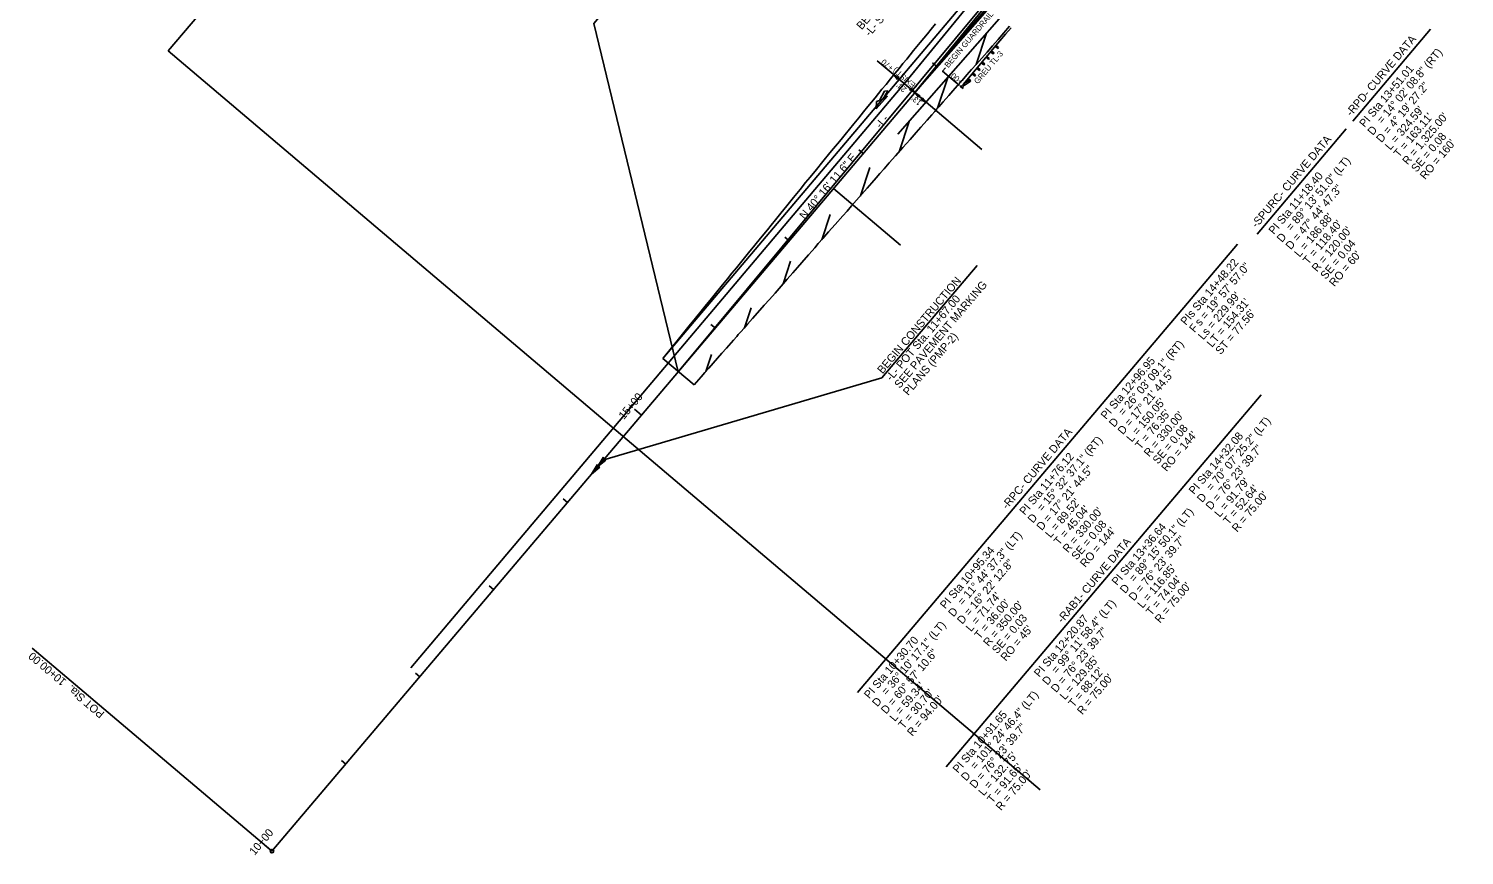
# Model space of a CAD drawing. Extents: x 1761082 to 1764358, y 421907 to 425434.
# Drawn here: x 1761082 to 1762338, y 421907 to 422631 of the extents above; entities that cross this region are included whole.
import ezdxf

# ---------------------------------------------------------------- set-up
doc = ezdxf.new("R2010")
doc.units = 0
for name, color, linetype in [('MARK HOOKS CENTER LEFT TURN ARROW CELL', 7, 'Continuous'), ('MARK HOOKS CENTER STRAIGHT LEFT TURN ARROW CELL', 7, 'Continuous'), ('MARK HOOKS STRAIGHT RIGHT TURN ARROW CELL', 7, 'Continuous'), ('MARK STRAIGHT RIGHT ARROW CELL', 7, 'Continuous'), ('MARK UTURN ARROW CELL', 7, 'Continuous'), ('Prop Horizontal Alignment Tick Large', 7, 'Continuous'), ('Prop Mkg 3ft Min Skp 3ft Wide White', 7, 'Continuous'), ('Prop Mkg 3ft Min Skp 9ft Wide White', 7, 'Continuous'), ('Prop Mkg Skp Wht', 7, 'Continuous'), ('Prop Mkg Solid White Multiple Diagonals V8i', 7, 'Continuous'), ('Prop Mkg Solid Yel Skip LT', 7, 'Continuous'), ('Prop Mkg Solid Yel Skip RT', 7, 'Continuous'), ('Prop Mkg Solid Yellow Diagonals', 7, 'Continuous'), ('Prop Mkg Solid Yellow Edge Line', 7, 'Continuous'), ('Prop Mkg Solid Yellow Lane Line', 7, 'Continuous'), ('Prop Mkg Yld Lin', 7, 'Continuous'), ('Prop Mkr Yel 40ft Spc', 7, 'Continuous'), ('Scratch_Level_0', 7, 'Continuous'), ('Typical Terminator CELL', 7, 'Continuous')]:
    doc.layers.add(name, color=color, linetype=linetype)

msp = doc.modelspace()

# ---------------------------------------------------------------- linework, layer by layer
at = {"layer": 'MARK HOOKS CENTER STRAIGHT LEFT TURN ARROW CELL'}
for p, q in [((1761876.3, 422597.5), (1761872.5, 422600.7)), ((1761811.6, 422521.2), (1761807.8, 422524.4)), ((1761747, 422444.9), (1761743.2, 422448.1)), ((1761682.4, 422368.6), (1761678.5, 422371.8)), ((1761553.1, 422216), (1761549.3, 422219.2)), ((1761488.4, 422139.7), (1761484.6, 422142.9)), ((1761423.8, 422063.4), (1761420, 422066.6)), ((1761359.2, 421987.1), (1761355.4, 421990.3))]:
    msp.add_line(p, q, dxfattribs=at)
at = {"layer": 'MARK STRAIGHT RIGHT ARROW CELL'}
msp.add_line((1761294.5, 421910.8), (1762673, 423537.9), dxfattribs=at)
at = {"layer": 'MARK UTURN ARROW CELL'}
for p, q in [((1762240.1, 422549.7), (1762308.2, 422630.1)), ((1762156.3, 422450.8), (1762234.4, 422542.9)), ((1761806.7, 422049.7), (1762139.1, 422442)), ((1761884.4, 421984.6), (1762160, 422310)), ((1761293.4, 421911.7), (1761084.7, 422088.5))]:
    msp.add_line(p, q, dxfattribs=at)
for points in [[(1761738.9, 422827.3), (1761576.1, 422635.1), (1761650, 422330.4)], [(1761911.5, 422423.4), (1761828, 422324.9), (1761584.7, 422253.3)]]:
    msp.add_lwpolyline(points, dxfattribs=at)
msp.add_circle((1761294.5, 421910.8), 1.5, dxfattribs=at)
at = {"layer": 'Prop Horizontal Alignment Tick Large'}
for p, q in [((1761617.7, 422292.3), (1761611.6, 422297.5)), ((1761294.5, 421910.8), (1761288.4, 421916))]:
    msp.add_line(p, q, dxfattribs=at)
at = {"layer": 'Prop Mkg 3ft Min Skp 3ft Wide White'}
msp.add_line((1761294.5, 421910.8), (1762673, 423537.9), dxfattribs=at)
at = {"layer": 'Prop Mkg 3ft Min Skp 9ft Wide White'}
msp.add_lwpolyline([(1761929.6, 422617.9), (1761931.4, 422619.9), (1761936.3, 422625.6), (1761941.3, 422631.3)], dxfattribs=at)
at = {"layer": 'Prop Mkg Skp Wht'}
msp.add_line((1761663.8, 422318.8), (1761636.4, 422342), dxfattribs=at)
for points in [[(1761875.1, 422634.8), (1761871.3, 422630.2), (1761867.9, 422626), (1761861.7, 422618.5), (1761855.8, 422611.3), (1761849.8, 422603.9), (1761846.5, 422600), (1761843.1, 422595.8), (1761839.5, 422591.3), (1761835.6, 422586.5), (1761831.8, 422581.8), (1761828.2, 422577.5), (1761822.2, 422570), (1761815.9, 422562.3), (1761812.1, 422557.7), (1761808, 422552.6), (1761803.7, 422547.4), (1761799.8, 422542.5), (1761796, 422537.9), (1761792.6, 422533.7), (1761789.2, 422529.7), (1761785.9, 422525.7), (1761782.7, 422521.8), (1761776.5, 422514.2), (1761770.8, 422507.4), (1761765.3, 422500.6), (1761761.4, 422495.8), (1761756.6, 422489.8), (1761750.8, 422482.7), (1761744.9, 422475.4), (1761739.6, 422469), (1761735.1, 422463.4), (1761731.3, 422458.7), (1761727.9, 422454.6), (1761722, 422447.3), (1761716.9, 422441.1), (1761711.4, 422434.4), (1761705.7, 422427.2), (1761700.8, 422421.3), (1761696.9, 422416.6), (1761692.9, 422411.7), (1761688.6, 422406.3), (1761682.6, 422398.9), (1761678.9, 422394.3), (1761674.7, 422389.1), (1761670.1, 422383.4), (1761665, 422377.2), (1761659.6, 422370.5), (1761653.7, 422363.3), (1761647.7, 422355.9), (1761641.6, 422348.3), (1761636.4, 422342)], [(1761663.8, 422318.8), (1761670, 422325.9), (1761673.3, 422329.6), (1761676.8, 422333.6), (1761680.5, 422337.8), (1761684.3, 422342.1), (1761688.2, 422346.5), (1761692.1, 422351), (1761698.3, 422358.1), (1761701.1, 422361.2), (1761702.5, 422362.8), (1761704.7, 422365.3), (1761707.5, 422368.4), (1761710.6, 422371.9), (1761714.9, 422376.8), (1761721.3, 422384.1), (1761725.2, 422388.6), (1761729.7, 422393.6), (1761734.6, 422399.2), (1761740, 422405.3), (1761745.3, 422411.4), (1761750.1, 422416.8), (1761754.4, 422421.7), (1761758.1, 422425.9), (1761763.8, 422432.5), (1761767, 422436.2), (1761769.4, 422438.9), (1761772.5, 422442.5), (1761776.5, 422447), (1761781.5, 422452.7), (1761787.3, 422459.3), (1761793.9, 422466.8), (1761797.6, 422470.9), (1761801.6, 422475.4), (1761805.9, 422480.4), (1761810.6, 422485.7), (1761815.2, 422490.9), (1761819.4, 422495.7), (1761823.1, 422500), (1761826.4, 422503.7), (1761830, 422507.8), (1761834.5, 422513), (1761840, 422519.2), (1761846.5, 422526.5), (1761852.8, 422533.7), (1761858.1, 422539.7), (1761862.3, 422544.4), (1761867.8, 422550.6), (1761871.7, 422555), (1761874.3, 422558), (1761876.3, 422560.4), (1761878, 422562.2), (1761879.7, 422564.1), (1761881.8, 422566.5), (1761886.7, 422572.1), (1761890.3, 422576.1), (1761894.3, 422580.7), (1761898.3, 422585.3), (1761902.4, 422590), (1761906.6, 422594.7), (1761910.9, 422599.6), (1761915.4, 422604.7), (1761920.1, 422610.1), (1761924.9, 422615.6), (1761929.9, 422621.2), (1761934.8, 422626.9), (1761939.8, 422632.6)]]:
    msp.add_lwpolyline(points, dxfattribs=at)
at = {"layer": 'Prop Mkg Solid White Multiple Diagonals V8i'}
for p, q in [((1761203.6, 422611), (1763595.3, 425434.2)), ((1761636.4, 422342), (1762107.9, 422898.7)), ((1761650, 422330.4), (1762065.6, 422830.3)), ((1761847.7, 422582.3), (1762056.3, 422837.9)), ((1761203.6, 422611), (1761966.6, 421964.6)), ((1761915.5, 422524.9), (1761856.9, 422574.6)), ((1761844.4, 422441), (1761785.8, 422490.7))]:
    msp.add_line(p, q, dxfattribs=at)
at = {"layer": 'Prop Mkg Solid Yel Skip RT'}
for p, q in [((1761824, 422602.5), (1761838, 422590.6)), ((1761838.5, 422590.1), (1761856.9, 422574.6)), ((1761866.7, 422566), (1761856.9, 422574.6)), ((1761856.9, 422574.6), (1761866.7, 422566))]:
    msp.add_line(p, q, dxfattribs=at)
msp.add_lwpolyline([(1761895.9, 422580.8), (1761881.2, 422593.3), (1761883.8, 422596.4)], dxfattribs=at)
at = {"layer": 'Prop Mkg Solid Yellow Diagonals'}
for p, q in [((1761826.1, 422567.8), (1761830.5, 422575.8)), ((1761833.4, 422576.2), (1761829.3, 422569)), ((1761830.5, 422575.8), (1761833.4, 422576.2)), ((1761832.9, 422571.4), (1761823.2, 422560.3)), ((1761823.2, 422560.3), (1761823.5, 422566.7)), ((1761823.5, 422566.7), (1761826.1, 422567.8)), ((1761829.3, 422569), (1761832.9, 422571.4))]:
    msp.add_line(p, q, dxfattribs=at)
at = {"layer": 'Prop Mkg Solid Yellow Edge Line'}
for p, q in [((1762055, 422836.3), (1761848.9, 422583.8)), ((1761848.9, 422583.8), (1761416.1, 422071.3))]:
    msp.add_line(p, q, dxfattribs=at)
at = {"layer": 'Prop Mkg Solid Yellow Lane Line'}
for points in [[(1761841.8, 422586.1), (1761838.5, 422590.1), (1761843, 422587.4), (1761841.9, 422587.2)], [(1761853.6, 422578.6), (1761856.9, 422574.6), (1761852.4, 422577.2), (1761853.5, 422577.5)], [(1761860.1, 422570.6), (1761856.9, 422574.6), (1761861.3, 422571.9), (1761860.3, 422571.6)], [(1761863.4, 422570.1), (1761866.7, 422566), (1761862.2, 422568.7), (1761863.3, 422569)]]:
    msp.add_lwpolyline(points, close=True, dxfattribs=at)
at = {"layer": 'Prop Mkg Yld Lin'}
for p, q in [((1761929.6, 422617.9), (1761899.4, 422582.1)), ((1761927.9, 422615.9), (1761927.3, 422615.2)), ((1761927.3, 422615.2), (1761929.6, 422613.2)), ((1761927.3, 422615.2), (1761928.4, 422614.2)), ((1761929.1, 422615), (1761927.3, 422615.2)), ((1761927.9, 422615.9), (1761930.2, 422614)), ((1761928.4, 422614.2), (1761927.9, 422615.9)), ((1761929.1, 422615), (1761928.4, 422614.2)), ((1761928.4, 422614.2), (1761930.2, 422614)), ((1761929.6, 422613.2), (1761929.1, 422615)), ((1761930.2, 422614), (1761929.6, 422613.2)), ((1761915.7, 422601.5), (1761915.1, 422600.7)), ((1761915.1, 422600.7), (1761917.4, 422598.8)), ((1761916.9, 422600.5), (1761915.1, 422600.7)), ((1761915.7, 422601.5), (1761918.1, 422599.5)), ((1761915.7, 422601.5), (1761916.3, 422599.7)), ((1761919.2, 422605.5), (1761921.5, 422603.6)), ((1761921, 422605.3), (1761919.2, 422605.5)), ((1761919.8, 422606.3), (1761922.1, 422604.3)), ((1761919.8, 422606.3), (1761920.3, 422604.5)), ((1761921, 422605.3), (1761920.3, 422604.5)), ((1761920.3, 422604.5), (1761922.1, 422604.3)), ((1761921.5, 422603.6), (1761921, 422605.3)), ((1761922.1, 422604.3), (1761921.5, 422603.6)), ((1761923.2, 422610.3), (1761925.6, 422608.4)), ((1761925, 422610.1), (1761923.2, 422610.3)), ((1761923.9, 422611.1), (1761926.2, 422609.1)), ((1761923.9, 422611.1), (1761924.4, 422609.4)), ((1761925, 422610.1), (1761924.4, 422609.4)), ((1761924.4, 422609.4), (1761926.2, 422609.1)), ((1761925.6, 422608.4), (1761925, 422610.1)), ((1761926.2, 422609.1), (1761925.6, 422608.4)), ((1761907, 422591.1), (1761909.3, 422589.1)), ((1761908.8, 422590.9), (1761907, 422591.1)), ((1761907.6, 422591.8), (1761909.9, 422589.9)), ((1761907.6, 422591.8), (1761908.1, 422590.1)), ((1761908.8, 422590.9), (1761908.1, 422590.1)), ((1761908.1, 422590.1), (1761909.9, 422589.9)), ((1761909.3, 422589.1), (1761908.8, 422590.9)), ((1761909.9, 422589.9), (1761909.3, 422589.1)), ((1761911, 422595.9), (1761913.4, 422593.9)), ((1761912.9, 422595.6), (1761911, 422595.9)), ((1761911.7, 422596.7), (1761914.1, 422594.6)), ((1761911.7, 422596.7), (1761912.2, 422594.9)), ((1761912.9, 422595.6), (1761912.2, 422594.9)), ((1761912.2, 422594.9), (1761914.1, 422594.6)), ((1761913.4, 422593.9), (1761912.9, 422595.6)), ((1761914.1, 422594.6), (1761913.4, 422593.9)), ((1761916.9, 422600.5), (1761916.3, 422599.7)), ((1761916.3, 422599.7), (1761918.1, 422599.5)), ((1761917.4, 422598.8), (1761916.9, 422600.5)), ((1761918.1, 422599.5), (1761917.4, 422598.8)), ((1761898.1, 422580.5), (1761896.7, 422580.2)), ((1761896.7, 422580.2), (1761898.9, 422578.3)), ((1761899.5, 422582.1), (1761898.1, 422580.5)), ((1761898.9, 422578.3), (1761899, 422579.7)), ((1761899, 422579.7), (1761900.4, 422581.2)), ((1761899.1, 422581.7), (1761900.3, 422580.8)), ((1761899.1, 422581.7), (1761900.9, 422581.5)), ((1761899.9, 422581.6), (1761899.5, 422582.1)), ((1761904.1, 422585.3), (1761899.8, 422582.5)), ((1761899.8, 422582.5), (1761900.9, 422581.5)), ((1761900.3, 422580.8), (1761899.8, 422582.5)), ((1761900.4, 422581.2), (1761899.9, 422581.6)), ((1761900.9, 422581.5), (1761900.3, 422580.8)), ((1761900.9, 422581.5), (1761900.6, 422581.2)), ((1761905.3, 422584.3), (1761900.9, 422581.5)), ((1761902.9, 422586.3), (1761905.3, 422584.3)), ((1761904.7, 422586), (1761902.9, 422586.3)), ((1761903.6, 422587), (1761905.9, 422585)), ((1761903.6, 422587), (1761904.1, 422585.3)), ((1761904.7, 422586), (1761904.1, 422585.3)), ((1761904.1, 422585.3), (1761905.9, 422585)), ((1761905.3, 422584.3), (1761904.7, 422586)), ((1761905.9, 422585), (1761905.3, 422584.3))]:
    msp.add_line(p, q, dxfattribs=at)
at = {"layer": 'Scratch_Level_0'}
for p, q in [((1761856.9, 422574.6), (1762095.5, 422846.9)), ((1761842.2, 422538.1), (1762105.3, 422838.4)), ((1761856.9, 422574.6), (1762065.6, 422830.3)), ((1761919.7, 422626.6), (1761910.7, 422599.3)), ((1761888.8, 422613.7), (1761893.1, 422615.9)), ((1761885.8, 422587.9), (1761876.9, 422561)), ((1761851.9, 422549.2), (1761843.2, 422522.8)), ((1761817.6, 422509.1), (1761809.3, 422484.2)), ((1761782.8, 422467.9), (1761775.6, 422445.9)), ((1761748.2, 422427), (1761741.7, 422407.3)), ((1761713.6, 422386.2), (1761707.9, 422368.8)), ((1761679, 422345.3), (1761674.1, 422330.5))]:
    msp.add_line(p, q, dxfattribs=at)
at = {"layer": 'Typical Terminator CELL'}
for points in [[(1761581.3, 422246.8), (1761574, 422240.7), (1761578.9, 422249), (1761579.4, 422247)], [(1761586.7, 422253.1), (1761579.4, 422247), (1761584.2, 422255.3), (1761584.7, 422253.3)]]:
    msp.add_lwpolyline(points, close=True, dxfattribs=at)

# ---------------------------------------------------------------- texts
at = {"layer": 'MARK HOOKS CENTER LEFT TURN ARROW CELL'}
msp.add_text('N 40%%d 16\' 11.6" E', height=7, rotation=49.7301, dxfattribs=at).set_placement((1761760.5, 422463.2))
at = {"layer": 'MARK HOOKS STRAIGHT RIGHT TURN ARROW CELL'}
for s, p in [('-L-', (1761827, 422542.8)), ('15+00', (1761602.4, 422288.1)), ('10+00', (1761279.3, 421906.7))]:
    msp.add_text(s, height=7, rotation=49.7301, dxfattribs=at).set_placement(p)
at = {"layer": 'MARK UTURN ARROW CELL'}
for s, rotation, p in [('BEGIN GRADE', 49.7301, (1761810.5, 422629.1)), ('-L- Sta. 21+69.00', 49.7301, (1761817.5, 422623.2)), ('BEGIN CONSTRUCTION', 49.7301, (1761828.7, 422328)), ('SEE PAVEMENT MARKING', 49.7301, (1761843.7, 422315.3)), ('-L- POT Sta. 11+67.00', 49.7301, (1761836.2, 422321.7)), ('PLANS (PMP-2)', 49.7301, (1761851.2, 422309)), ('POT Sta.  10+00.00', 139.7301, (1761148.5, 422031.9))]:
    msp.add_text(s, height=7, rotation=rotation, dxfattribs=at).set_placement(p)
at = {"layer": 'Prop Mkg Solid Yel Skip LT'}
for s, rotation, p in [('BEGIN GUARDRAIL', 49.7301, (1761886.2, 422595.9)), ('+70', 139.7301, (1761838.8, 422597)), ('(EXIST.)', 139.7301, (1761859.8, 422580.5)), ('+00', 139.7301, (1761899.6, 422584.9)), ("24'", 139.7301, (1761850.2, 422578.1)), ("13'", 138.7805, (1761863.4, 422566.5))]:
    msp.add_text(s, height=5, rotation=rotation, dxfattribs=at).set_placement(p)
at = {"layer": 'Prop Mkg Yld Lin'}
msp.add_text('GREU TL-3', height=5, rotation=49.7301, dxfattribs=at).set_placement((1761912, 422581.7))
at = {"layer": 'Prop Mkr Yel 40ft Spc'}
for s, rotation, p in [('-RPD- CURVE DATA', 49.7301, (1762238.6, 422553.3)), ('= 14%%d 02\' 08.8" (RT)', 49.7992, (1762265.7, 422546.7)), ('PI Sta 13+51.01', 49.7992, (1762250.4, 422543.7)), ('D = 4%%d 19\' 27.2"', 49.7992, (1762265.2, 422530.3)), ("L = 324.59'", 49.7992, (1762272.9, 422523.8)), ("T = 163.11'", 49.7992, (1762280.5, 422517.4)), ("R = 1,325.00'", 49.7992, (1762288.1, 422510.9)), ('D', 49.7992, (1762257.6, 422536.7)), ('SE = 0.08', 49.7992, (1762295.8, 422504.4)), ('-SPURC- CURVE DATA', 49.7301, (1762155.9, 422455.7)), ("RO = 160'", 49.7992, (1762303.4, 422498)), ('= 89%%d 13\' 51.0" (LT)', 49.755, (1762186.3, 422453)), ('PI Sta 11+18.40', 49.755, (1762171, 422450)), ('D = 47%%d 44\' 47.3"', 49.755, (1762185.9, 422436.6)), ("L = 186.88'", 49.755, (1762193.5, 422430.1)), ("T = 118.40'", 49.755, (1762201.1, 422423.7)), ('D', 49.755, (1762178.2, 422443)), ("R = 120.00'", 49.755, (1762208.8, 422417.2)), ('SE = 0.04', 49.755, (1762216.4, 422410.7)), ('PIs Sta 14+48.22', 49.7163, (1762094, 422370.6)), ('s = 19%%d 57\' 57.0"', 49.7163, (1762106.5, 422369.9)), ("RO = 60'", 49.755, (1762224, 422404.3)), ("Ls = 229.99'", 49.7163, (1762109.3, 422357.7)), ("LT = 154.31'", 49.7163, (1762116.9, 422351.2)), ("ST = 77.56'", 49.7163, (1762124.5, 422344.8)), ('F', 49.7163, (1762101.6, 422364.2)), ('= 26%%d 03\' 09.1" (RT)', 49.7627, (1762039.5, 422291.3)), ('PI Sta 12+96.95', 49.7627, (1762024.2, 422288.2)), ('D = 17%%d 21\' 44.5"', 49.7627, (1762039, 422274.8)), ("L = 150.05'", 49.7627, (1762046.7, 422268.3)), ('D', 49.7627, (1762031.4, 422281.3)), ("T = 76.35'", 49.7627, (1762054.3, 422261.9)), ("R = 330.00'", 49.7627, (1762061.9, 422255.4)), ('= 70%%d 07\' 25.2" (LT)', 49.7721, (1762116.5, 422225.4)), ('-RPC- CURVE DATA', 49.7301, (1761937.6, 422209.5)), ('SE = 0.08', 49.7627, (1762069.6, 422249)), ("RO = 144'", 49.7627, (1762077.2, 422242.5)), ('PI Sta 14+32.08', 49.7721, (1762101.2, 422222.4)), ('= 15%%d 32\' 37.1" (RT)', 49.7415, (1761968.4, 422207.4)), ('D = 76%%d 23\' 39.7"', 49.7721, (1762116, 422208.9)), ('PI Sta 11+76.12', 49.7415, (1761953.1, 422204.4)), ('D = 17%%d 21\' 44.5"', 49.7415, (1761968, 422190.9)), ("L = 91.79'", 49.7721, (1762123.6, 422202.5)), ("T = 52.64'", 49.7721, (1762131.3, 422196)), ("R = 75.00'", 49.7721, (1762138.9, 422189.5)), ("L = 89.52'", 49.7415, (1761975.6, 422184.5)), ("T = 45.04'", 49.7415, (1761983.2, 422178)), ("R = 330.00'", 49.7415, (1761990.9, 422171.5)), ('D', 49.7721, (1762108.4, 422215.4)), ('D', 49.7415, (1761960.3, 422197.4)), ('SE = 0.08', 49.7415, (1761998.5, 422165.1)), ('= 89%%d 15\' 50.1" (LT)', 49.7457, (1762049, 422145.8)), ('= 11%%d 44\' 37.3" (LT)', 49.7204, (1761898.9, 422125.3)), ("RO = 144'", 49.7415, (1762006.1, 422158.6)), ('PI Sta 13+36.64', 49.7457, (1762033.8, 422142.8)), ('D = 76%%d 23\' 39.7"', 49.7457, (1762048.6, 422129.3)), ('PI Sta 10+95.34', 49.7204, (1761883.6, 422122.3)), ('-RAB1- CURVE DATA', 49.7301, (1761986, 422109.9)), ('D = 16%%d 22\' 12.8"', 49.7204, (1761898.5, 422108.9)), ("L = 116.85'", 49.7457, (1762056.2, 422122.9)), ("T = 74.04'", 49.7457, (1762063.8, 422116.4)), ("L = 71.74'", 49.7204, (1761906.1, 422102.4)), ('D', 49.7457, (1762041, 422135.8)), ("R = 75.00'", 49.7457, (1762071.5, 422109.9)), ('D', 49.7204, (1761890.8, 422115.3)), ("T = 36.00'", 49.7204, (1761913.7, 422095.9)), ("R = 350.00'", 49.7204, (1761921.4, 422089.5)), ('= 99%%d 11\' 58.4" (LT)', 49.7674, (1761981.1, 422065.6)), ('= 36%%d 10\' 17.1" (LT)', 49.7266, (1761832.3, 422046.7)), ('SE = 0.03', 49.7204, (1761929, 422083)), ('PI Sta 12+20.87', 49.7674, (1761965.8, 422062.6)), ('PI Sta 10+30.70', 49.7266, (1761817.1, 422043.7)), ("RO = 45'", 49.7204, (1761936.6, 422076.6)), ('D = 76%%d 23\' 39.7"', 49.7674, (1761980.6, 422049.1)), ('D = 60%%d 57\' 10.6"', 49.7266, (1761831.9, 422030.3)), ("L = 129.85'", 49.7674, (1761988.3, 422042.7)), ('D', 49.7674, (1761973, 422055.6)), ("T = 88.12'", 49.7674, (1761995.9, 422036.2)), ("R = 75.00'", 49.7674, (1762003.5, 422029.7)), ("L = 59.34'", 49.7266, (1761839.5, 422023.8)), ("T = 30.70'", 49.7266, (1761847.1, 422017.3)), ('= 101%%d 24\' 46.4" (LT)', 49.7704, (1761910, 421981.7)), ('D', 49.7266, (1761824.2, 422036.7)), ("R = 94.00'", 49.7266, (1761854.8, 422010.9)), ('PI Sta 10+91.65', 49.7704, (1761894.7, 421978.6)), ('D = 76%%d 23\' 39.7"', 49.7704, (1761909.5, 421965.2)), ("L = 132.75'", 49.7704, (1761917.2, 421958.7)), ("T = 91.65'", 49.7704, (1761924.8, 421952.3)), ('D', 49.7704, (1761901.9, 421971.7)), ("R = 75.00'", 49.7704, (1761932.4, 421945.8))]:
    msp.add_text(s, height=7, rotation=rotation, dxfattribs=at).set_placement(p)

doc.saveas('drawing.dxf')
